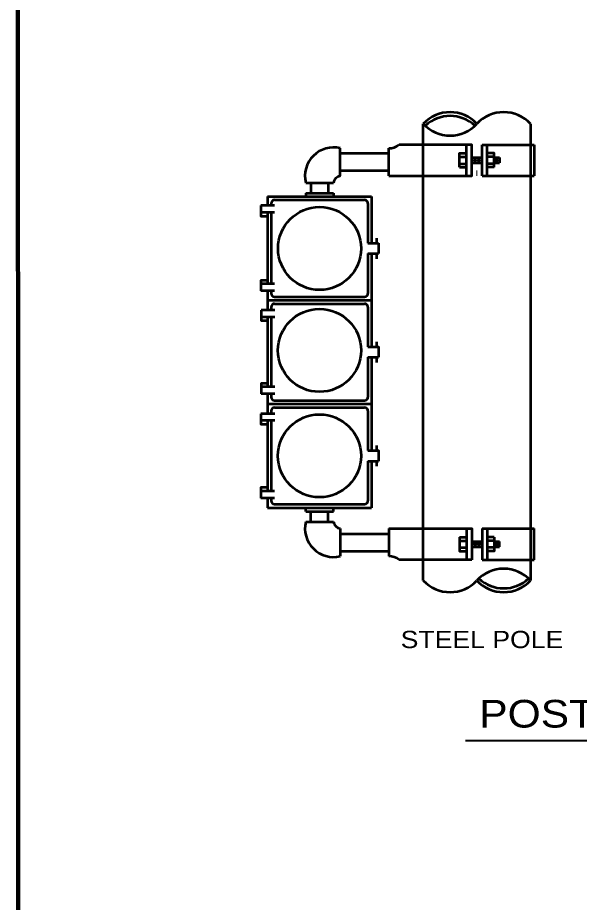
# Model space of a CAD drawing. Extents: x -370 to 486, y -203 to 341.
# Drawn here: x -312.3 to -214.9, y -37.7 to 115.9 of the extents above; entities that cross this region are included whole.
import ezdxf
from ezdxf.enums import TextEntityAlignment as Align

# ---------------------------------------------------------------- set-up
doc = ezdxf.new("R2010")
doc.units = 0
doc.header["$LTSCALE"] = 0.96
doc.layers.add('1', color=7, linetype='Continuous', lineweight=53)

msp = doc.modelspace()

# ---------------------------------------------------------------- linework, layer by layer
at = {"layer": '1'}
for p, q in [((-241.9446, 18.1943), (-241.9446, 97.4253)), ((-223.3446, 97.4253), (-223.3446, 18.1943)), ((-234.4446, 88.4253), (-234.4446, 93.8253)), ((-231.7446, 88.4253), (-231.7446, 93.8253)), ((-231.7446, 93.8253), (-222.7446, 93.8253)), ((-230.8446, 88.4253), (-230.8446, 93.8253)), ((-222.7446, 93.8253), (-222.7446, 88.4253)), ((-256.3446, 88.4253), (-256.3446, 93.2253)), ((-256.3446, 92.3253), (-247.9446, 92.3253)), ((-247.9446, 88.4253), (-247.9446, 93.2253)), ((-235.6446, 91.7253), (-234.4446, 91.7253)), ((-233.5446, 91.5753), (-231.7446, 91.5753)), ((-233.5446, 90.6753), (-231.7446, 90.6753)), ((-233.2446, 90.9753), (-233.2446, 91.2753)), ((-232.9446, 90.6753), (-232.9446, 91.5753)), ((-232.6446, 90.9753), (-232.6446, 91.2753)), ((-232.3446, 90.6753), (-232.3446, 91.5753)), ((-232.0446, 90.9753), (-232.0446, 91.2753)), ((-229.6482, 91.7253), (-230.8482, 91.7253)), ((-229.6482, 90.6753), (-228.7482, 90.6753)), ((-229.4232, 91.2753), (-229.4232, 90.9753)), ((-229.1982, 90.6753), (-229.1982, 91.5753)), ((-228.9732, 91.2753), (-228.9732, 90.9753)), ((-228.7482, 91.5753), (-228.7482, 90.6753)), ((-256.3446, 89.3253), (-247.9446, 89.3253)), ((-235.6446, 90.5253), (-234.4446, 90.5253)), ((-235.6446, 89.9253), (-234.4446, 89.9253)), ((-229.6482, 90.5253), (-230.8482, 90.5253)), ((-229.6482, 89.9253), (-230.8482, 89.9253)), ((-231.7446, 88.4253), (-222.7446, 88.4253)), ((-262.3446, 87.2253), (-257.5446, 87.2253)), ((-261.4446, 87.2253), (-261.4446, 85.4253)), ((-258.4446, 87.2253), (-258.4446, 85.4253)), ((-268.9446, 84.8253), (-250.9446, 84.8253)), ((-268.9446, 84.8253), (-268.9446, 83.2413)), ((-262.3446, 85.4253), (-257.5446, 85.4253)), ((-262.3446, 85.4253), (-262.3446, 84.8253)), ((-257.5446, 85.4253), (-257.5446, 84.8253)), ((-250.9446, 84.8253), (-250.9446, 76.7253)), ((-267.7446, 83.2413), (-270.1446, 83.2413)), ((-268.3446, 83.6253), (-268.3446, 83.2413)), ((-267.7446, 84.2253), (-252.1446, 84.2253)), ((-251.5446, 83.6253), (-251.5446, 76.7253)), ((-267.7446, 82.0413), (-270.1446, 82.0413)), ((-268.9446, 82.0413), (-268.9446, 69.6562)), ((-268.3446, 82.0413), (-268.3446, 69.6562)), ((-250.0446, 77.6253), (-250.0446, 76.7253)), ((-251.5446, 76.7253), (-249.7446, 76.7253)), ((-249.7446, 76.7253), (-249.7446, 74.9253)), ((-251.5446, 74.9253), (-251.5446, 68.0253)), ((-251.5446, 74.9253), (-249.7446, 74.9253)), ((-250.9446, 74.9253), (-250.9446, 58.7253)), ((-250.0446, 74.9253), (-250.0446, 74.0253)), ((-267.7446, 69.6562), (-270.1446, 69.6562)), ((-267.7446, 68.4562), (-270.1446, 68.4562)), ((-268.9446, 68.4562), (-268.9446, 65.1105)), ((-268.3446, 68.4562), (-268.3446, 68.0253)), ((-268.9446, 66.8253), (-250.9446, 66.8253)), ((-267.7446, 67.4253), (-252.1446, 67.4253)), ((-267.7446, 66.2253), (-252.1446, 66.2253)), ((-267.6947, 65.1105), (-270.0947, 65.1105)), ((-268.3446, 65.6253), (-268.3446, 65.1105)), ((-251.5446, 65.6253), (-251.5446, 58.7253)), ((-267.6947, 63.9105), (-270.0947, 63.9105)), ((-268.9446, 63.9105), (-268.9446, 51.7917)), ((-268.3446, 63.9105), (-268.3446, 51.7917)), ((-250.0446, 59.6253), (-250.0446, 58.7253)), ((-251.5446, 56.9253), (-249.7446, 56.9253)), ((-251.5446, 56.9253), (-251.5446, 50.0253)), ((-250.9446, 56.9253), (-250.9446, 40.7253)), ((-250.0446, 56.9253), (-250.0446, 56.0253)), ((-267.6947, 51.7917), (-270.0947, 51.7917)), ((-267.6947, 50.5917), (-270.0947, 50.5917)), ((-268.9446, 50.5917), (-268.9446, 47.1425)), ((-268.3446, 50.5917), (-268.3446, 50.0253)), ((-267.7446, 49.4253), (-252.1446, 49.4253)), ((-268.9446, 48.8253), (-250.9446, 48.8253)), ((-268.3446, 47.6253), (-268.3446, 47.1425)), ((-267.7446, 48.2253), (-252.1446, 48.2253)), ((-251.5446, 47.6253), (-251.5446, 40.7253)), ((-267.7147, 47.1425), (-270.1147, 47.1425)), ((-267.7147, 45.9425), (-270.1147, 45.9425)), ((-268.9446, 45.9425), (-268.9446, 33.7055)), ((-268.3446, 45.9425), (-268.3446, 33.7055)), ((-250.0446, 41.6253), (-250.0446, 40.7253)), ((-251.5446, 38.9253), (-249.7446, 38.9253)), ((-251.5446, 38.9253), (-251.5446, 32.0253)), ((-250.9446, 38.9253), (-250.9446, 30.8253)), ((-250.0446, 38.9253), (-250.0446, 38.0253)), ((-267.7463, 33.7055), (-270.1463, 33.7055)), ((-267.7463, 32.5055), (-270.1463, 32.5055)), ((-268.9446, 32.5055), (-268.9446, 30.8253)), ((-268.3446, 32.5055), (-268.3446, 32.0253)), ((-268.9446, 30.8253), (-250.9446, 30.8253)), ((-267.7446, 31.4253), (-252.1446, 31.4253)), ((-262.3446, 30.1943), (-262.3446, 30.7943)), ((-257.5446, 30.1943), (-257.5446, 30.7943)), ((-262.3446, 30.1943), (-257.5446, 30.1943)), ((-261.4446, 28.3943), (-261.4446, 30.1943)), ((-258.4446, 28.3943), (-258.4446, 30.1943)), ((-262.3446, 28.3943), (-257.5446, 28.3943)), ((-256.3446, 27.1943), (-256.3446, 22.3943)), ((-256.3446, 26.2943), (-247.9446, 26.2943)), ((-247.9446, 27.1943), (-247.9446, 22.3943)), ((-234.4446, 27.1943), (-234.4446, 21.7943)), ((-231.7446, 27.1943), (-231.7446, 21.7943)), ((-231.7446, 27.1943), (-222.7446, 27.1943)), ((-230.8446, 27.1943), (-230.8446, 21.7943)), ((-222.7446, 21.7943), (-222.7446, 27.1943)), ((-235.6446, 25.6943), (-234.4446, 25.6943)), ((-235.6446, 25.0943), (-234.4446, 25.0943)), ((-233.5446, 24.9443), (-231.7446, 24.9443)), ((-233.2446, 24.6443), (-233.2446, 24.3443)), ((-232.9446, 24.9443), (-232.9446, 24.0443)), ((-232.6446, 24.6443), (-232.6446, 24.3443)), ((-232.3446, 24.9443), (-232.3446, 24.0443)), ((-232.0446, 24.6443), (-232.0446, 24.3443)), ((-229.6482, 25.6943), (-230.8482, 25.6943)), ((-229.6482, 25.0943), (-230.8482, 25.0943)), ((-229.6482, 24.9443), (-228.7482, 24.9443)), ((-229.4232, 24.3443), (-229.4232, 24.6443)), ((-229.1982, 24.9443), (-229.1982, 24.0443)), ((-228.9732, 24.3443), (-228.9732, 24.6443)), ((-228.7482, 24.0443), (-228.7482, 24.9443)), ((-256.3446, 23.2943), (-247.9446, 23.2943)), ((-235.6446, 23.8943), (-234.4446, 23.8943)), ((-233.5446, 24.0443), (-231.7446, 24.0443)), ((-229.6482, 23.8943), (-230.8482, 23.8943)), ((-229.6482, 24.0443), (-228.7482, 24.0443)), ((-233.5446, 21.7943), (-246.1446, 21.7943)), ((-231.7446, 21.7943), (-222.7446, 21.7943))]:
    msp.add_line(p, q, dxfattribs=at)
at = {"layer": '1', "lineweight": 13}
msp.add_line((-232.6446, 88.4253), (-232.6446, 89.3683), dxfattribs=at)
at = {"layer": '1', "lineweight": 40}
msp.add_line((-234.6348, -9.5781), (-147.6889, -9.5781), dxfattribs=at)
at = {"layer": '1', "lineweight": 158}
msp.add_lwpolyline([(479.406, 334.9398), (-312.294, 334.8398), (-312.194, -191.1602)], dxfattribs=at)
at = {"layer": '1'}
for points in [[(-247.9446, 88.4253), (-233.5446, 88.4253), (-233.5446, 93.8253), (-246.1446, 93.8253)], [(-235.6446, 89.9253), (-235.6446, 92.3253), (-234.4446, 92.3253)], [(-229.6482, 89.9253), (-229.6482, 92.3253), (-230.8482, 92.3253)], [(-229.6482, 91.5753), (-229.1982, 91.5753), (-228.7482, 91.5753)], [(-270.1446, 83.2413), (-270.1446, 81.4413), (-268.9446, 81.4413)], [(-268.9446, 70.2562), (-270.1446, 70.2562), (-270.1446, 68.4562)], [(-270.0947, 65.1105), (-270.0947, 63.3105), (-268.8947, 63.3105)], [(-251.5446, 58.7253), (-249.7446, 58.7253), (-249.7446, 56.9253)], [(-268.8947, 52.3917), (-270.0947, 52.3917), (-270.0947, 50.5917)], [(-270.1147, 47.1425), (-270.1147, 45.3425), (-268.9147, 45.3425)], [(-251.5446, 40.7253), (-249.7446, 40.7253), (-249.7446, 38.9253)], [(-268.9463, 34.3055), (-270.1463, 34.3055), (-270.1463, 32.5055)], [(-247.9446, 27.1943), (-233.5446, 27.1943), (-233.5446, 21.7943)], [(-235.6446, 25.6943), (-235.6446, 23.2943), (-234.4446, 23.2943)], [(-229.6482, 25.6943), (-229.6482, 23.2943), (-230.8482, 23.2943)]]:
    msp.add_lwpolyline(points, dxfattribs=at)
for centre in [(-259.9371, 75.8182), (-259.9508, 58.1258), (-259.9513, 39.8281)]:
    msp.add_circle(centre, 7.2, dxfattribs=at)
for centre, radius, start, end in [((-237.2946, 93.1113), 6.3555, 42.97503, 137.02497), ((-237.2946, 92.4445), 6.3555, 47.11243, 132.88757), ((-228.0088, 93.1113), 6.3555, 42.97503, 137.02497), ((-237.2946, 101.7577), 6.3555, 222.97503, 317.02497), ((-247.7902, 95.762), 2.5414, 266.51631, 310.35359), ((-257.478, 88.3587), 4.9969, 76.89015, 193.10985), ((-256.0044, 86.8851), 1.5774, 102.45679, 167.54321), ((-267.7446, 83.6253), 0.6, 90, 180), ((-252.1446, 83.6253), 0.6, 0, 90), ((-267.7446, 68.0253), 0.6, 180, 270), ((-252.1446, 68.0253), 0.6, 270, 0), ((-267.7446, 65.6253), 0.6, 90, 180), ((-252.1446, 65.6253), 0.6, 0, 90), ((-267.7446, 50.0253), 0.6, 180, 270), ((-252.1446, 50.0253), 0.6, 270, 0), ((-267.7446, 47.6253), 0.6, 90, 180), ((-252.1446, 47.6253), 0.6, 0, 90), ((-267.7446, 32.0253), 0.6, 180, 270), ((-252.1446, 32.0253), 0.6, 270, 0), ((-257.478, 27.2609), 4.9969, 166.89015, 283.10985), ((-256.0044, 28.7345), 1.5774, 192.45679, 257.54321), ((-247.7902, 19.8576), 2.5414, 49.64641, 93.48369), ((-228.0088, 13.8803), 6.3555, 42.97503, 137.02497), ((-228.0088, 23.1935), 6.3555, 227.11243, 312.88757), ((-237.2946, 22.5267), 6.3555, 222.97503, 317.02497), ((-228.0088, 22.5267), 6.3555, 222.97503, 317.02497)]:
    msp.add_arc(centre, radius, start, end, dxfattribs=at)

# ---------------------------------------------------------------- texts
at = {"layer": '1', "width": 1.15}
for s, height, p in [('STEEL POLE', 3, (-231.7726, 6.4594)), ('POST MOUNT METHOD', 4.8, (-190.6266, -7.3253))]:
    msp.add_text(s, height=height, dxfattribs=at).set_placement(p, align=Align.CENTER)

doc.saveas('drawing.dxf')
